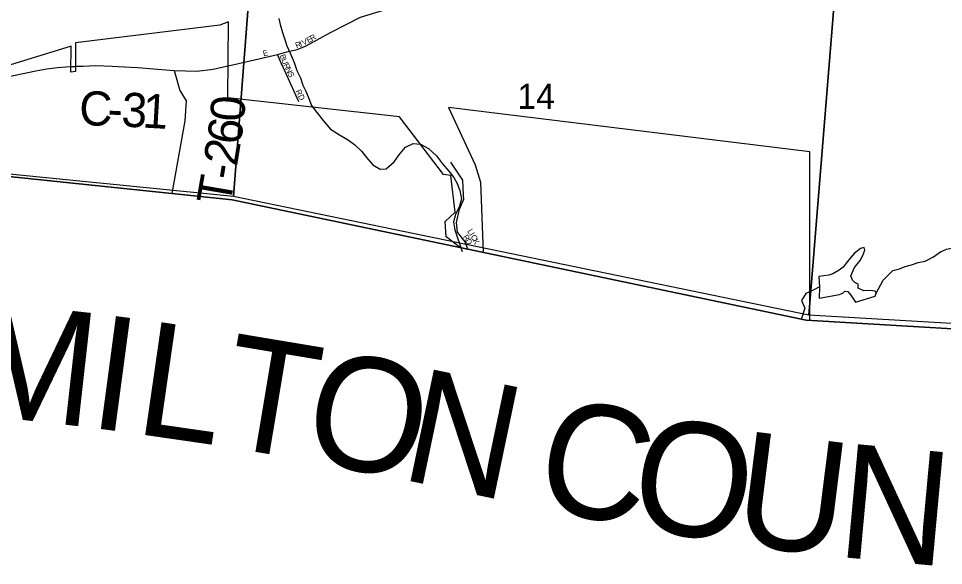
# Model space of a CAD drawing. Extents: x 1310247 to 1552180, y 377264 to 706493.
# Drawn here: x 1367792 to 1375909, y 481326 to 486127 of the extents above; entities that cross this region are included whole.
import ezdxf

# ---------------------------------------------------------------- set-up
doc = ezdxf.new("R2010")
doc.units = 0
for name, color, linetype in [('GM_X_Adjacent_County', 7, 'Continuous'), ('GM_X_Adjacent_County_Text', 7, 'Continuous'), ('GM_X_City_Street', 7, 'Continuous'), ('GM_X_City_Street_Text', 7, 'Continuous'), ('GM_X_Corporation', 7, 'Continuous'), ('GM_X_County', 7, 'Continuous'), ('GM_X_County_Road', 7, 'Continuous'), ('GM_X_County_Road_Text', 7, 'Continuous'), ('GM_X_Minor_River', 7, 'Continuous'), ('GM_X_Section', 7, 'Continuous'), ('GM_X_Section_Text', 7, 'Continuous'), ('GM_X_Township', 7, 'Continuous'), ('GM_X_Township_Road', 7, 'Continuous'), ('GM_X_Township_Road_Text', 7, 'Continuous')]:
    doc.layers.add(name, color=color, linetype=linetype)

msp = doc.modelspace()

# ---------------------------------------------------------------- linework, layer by layer
at = {"layer": 'GM_X_Adjacent_County'}
msp.add_lwpolyline([(1367312.1, 484779.9), (1369137.5, 484590.3), (1369667, 484535.3), (1371735.5, 484101.4), (1374704, 483478.8), (1379249.6, 483210.6), (1380075.5, 483161.9)], dxfattribs=at)
at = {"layer": 'GM_X_City_Street'}
for points in [[(1369824.4, 485755.1), (1369824.9, 485755.2), (1370064.8, 485810), (1370147.3, 485834.3), (1370237.5, 485855.9), (1370317, 485887.3), (1370530.1, 486004.4), (1370794.6, 486138), (1370994, 486198.7), (1371535, 486356), (1371847.8, 486445.8), (1372298, 486578.9), (1372444.1, 486634.9), (1372470.8, 486645.1)], [(1370250.9, 485396.8), (1370143.3, 485635.5), (1370099, 485728.7), (1370064.8, 485810)], [(1368250.3, 485704.3), (1368286.7, 485706.7), (1368303.8, 485707.4)], [(1371735.5, 484101.4), (1371710.5, 484166.5), (1371644.4, 484250.4), (1371636.5, 484337), (1371661.5, 484452.8), (1371699.8, 484542.3), (1371698.2, 484575.2), (1371698.1, 484576.3)]]:
    msp.add_lwpolyline(points, dxfattribs=at)
at = {"layer": 'GM_X_Corporation'}
msp.add_lwpolyline([(1380075.5, 483161.9), (1374735.4, 483477), (1374735, 484955.7), (1371565.2, 485345), (1371800.3, 484842.4), (1371847.2, 484689.1), (1371868.8, 484073.5), (1371669.5, 484115.3), (1371544.1, 484210.1), (1371536.3, 484343.6), (1371622.6, 484426.9), (1371587, 484749.7), (1371520.5, 484757.8), (1371135.2, 485263), (1369628.2, 485429.2), (1369633.9, 486096.7), (1369559.8, 486069.7), (1368293.4, 485914.2), (1368293.5, 485660.9), (1368251.6, 485655.1), (1368253.8, 485882.6), (1367101.3, 485530.2)], dxfattribs=at)
at = {"layer": 'GM_X_County'}
msp.add_lwpolyline([(1380075.5, 483161.9), (1379249.6, 483210.6), (1374704, 483478.8), (1371735.5, 484101.4), (1369667, 484535.3), (1369137.5, 484590.3), (1367312.1, 484779.9)], dxfattribs=at)
at = {"layer": 'GM_X_County_Road'}
for points in [[(1368838.8, 485695.4), (1368976.1, 485686.2), (1369159.3, 485671.2), (1369357.4, 485663.4), (1369500.7, 485681.3), (1369722.3, 485731.3), (1369824.4, 485755.1)], [(1366607, 484844.3), (1366958.7, 485194.1), (1367113.7, 485359.7), (1367209.7, 485442.2), (1367283.7, 485480.2), (1367408.4, 485524.6), (1367707.3, 485617.1), (1367943.1, 485667.1), (1368041.2, 485685.1), (1368135.6, 485695.5), (1368208.3, 485701.5), (1368250.3, 485704.3)], [(1368303.8, 485707.4), (1368359.4, 485709.7), (1368472.1, 485714.5), (1368615.4, 485709.7), (1368775.8, 485699.6), (1368838.8, 485695.4)]]:
    msp.add_lwpolyline(points, dxfattribs=at)
at = {"layer": 'GM_X_Minor_River'}
for points in [[(1370075.4, 486127.4), (1370087.9, 486072.8), (1370108.1, 486003.9), (1370128.5, 485941.1), (1370147.1, 485886.3), (1370175.4, 485821.2), (1370211.4, 485741.9), (1370235.5, 485670.9), (1370265.9, 485605.8), (1370288.2, 485540.8), (1370312.9, 485489.9), (1370339.2, 485424.9), (1370363.6, 485362), (1370410.1, 485300.4), (1370464.4, 485230.6), (1370530.6, 485156.5), (1370609.5, 485106.1), (1370680.6, 485064), (1370739.7, 485022.2), (1370806.2, 484960.1), (1370846.9, 484906.8), (1370901.3, 484841), (1370964.6, 484805.1), (1371018.8, 484807.6), (1371088.7, 484868.1), (1371130.4, 484927.2), (1371188.5, 484998), (1371255.6, 485030.4), (1371319.7, 485024.6), (1371388.9, 484984.6), (1371461.4, 484920.3), (1371511.7, 484852.6), (1371568.1, 484786.8), (1371612.8, 484731.3), (1371641.4, 484678.3), (1371663.8, 484617.4), (1371679.9, 484544.6), (1371662.1, 484478.8), (1371628, 484405.3), (1371610.2, 484341.5), (1371620.3, 484270.9), (1371686.8, 484082.2)], [(1374821.5, 483770.4), (1374818.9, 483672), (1374996.3, 483703.4), (1375024.8, 483716.7), (1375043.3, 483734.3), (1375069.3, 483731.6), (1375096.5, 483698.7), (1375119.6, 483661.9), (1375137, 483637.3), (1375311, 483690.9), (1375317.7, 483714.8), (1375308.2, 483733.2), (1375262.2, 483740.5), (1375210, 483737.8), (1375160.4, 483759.3), (1375159.3, 483795.5), (1375131.6, 483808.3), (1375110.2, 483831), (1375095.1, 483869.6), (1375127.2, 483941), (1375177.1, 484004), (1375202.3, 484047.5), (1375217.6, 484093.4), (1375214.3, 484117.6), (1375179.9, 484108.4), (1375126.5, 484063.7), (1375089.3, 484024.5)], [(1375317.7, 483714.8), (1375379, 483829.7), (1375465.6, 483913.8), (1375522.2, 483930.4), (1375572.9, 483949.1), (1375627.5, 483965.7), (1375686.2, 483984.2), (1375748.8, 483996.6), (1375822.1, 484034.8), (1375881.5, 484079.5), (1375936.3, 484102.1), (1375994.8, 484114.6), (1376063.2, 484120.8), (1376132.1, 484143)], [(1375089.3, 484024.5), (1375056, 483979.1), (1375028.9, 483943.7), (1374994.1, 483918.5), (1374937.1, 483885.9), (1374902.6, 483874.8), (1374816, 483863), (1374821.5, 483770.4)], [(1374821.5, 483770.4), (1374770.7, 483745.7), (1374701.6, 483713.4), (1374663.8, 483652.1), (1374692, 483583), (1374661.1, 483484.4)]]:
    msp.add_lwpolyline(points, dxfattribs=at)
at = {"layer": 'GM_X_Section'}
for points in [[(1375156.7, 488824.4), (1374727.4, 483521.8), (1369678.8, 484563.3), (1369911.3, 487554.2)], [(1369911.3, 487554.2), (1369678.8, 484563.3), (1365682.4, 484963.6)]]:
    msp.add_lwpolyline(points, dxfattribs=at)
msp.add_lwpolyline([(1375156.7, 488824.4), (1380602.9, 488643.8), (1380084.6, 483209.4), (1374727.4, 483521.8)], close=True, dxfattribs=at)
at = {"layer": 'GM_X_Township'}
msp.add_lwpolyline([(1380075.5, 483161.9), (1379249.6, 483210.6), (1374704, 483478.8), (1371735.5, 484101.4), (1369667, 484535.3), (1369137.5, 484590.3), (1367312.1, 484779.9)], dxfattribs=at)
at = {"layer": 'GM_X_Township_Road'}
for points in [[(1369159.3, 485671.2), (1369209, 485496.1), (1369262.6, 485404.2), (1369251.6, 485229.9), (1369137.5, 484590.3)], [(1371698.1, 484576.3), (1371691.8, 484707.1), (1371585.4, 484864.4)]]:
    msp.add_lwpolyline(points, dxfattribs=at)

# ---------------------------------------------------------------- texts
at = {"layer": 'GM_X_Adjacent_County_Text'}
for s, rotation, p in [('M', 353.59871, (1367318.2, 482660.6)), ('I', 352.39247, (1368392.7, 482540.1)), ('L', 351.78594, (1368795.5, 482486.3)), ('T', 350.50227, (1369530, 482380.4)), ('O', 348.88243, (1370260.4, 482258.3)), ('N', 348.18065, (1371125, 482088.4)), ('C', 348.46218, (1372293.3, 481843.8)), ('O', 350.29417, (1373125.2, 481674.5)), ('U', 352.83993, (1374044.9, 481518.3)), ('N', 354.74033, (1374958.4, 481404.2))]:
    msp.add_text(s, height=1000, rotation=rotation, dxfattribs=at).set_placement(p)
at = {"layer": 'GM_X_City_Street_Text'}
for s, rotation, p in [('E', 29.40387, (1370336.4, 485908.9)), ('R', 29.48054, (1370367.1, 485926.3)), ('R', 21.40454, (1370232.7, 485864.1)), ('I', 21.40429, (1370269.5, 485878.6)), ('V', 25.79118, (1370293.8, 485888.2)), ('E', 14.04106, (1369943.4, 485794)), ('B', 290.68965, (1370082.1, 485801.4)), ('U', 292.39156, (1370096.7, 485762.8)), ('R', 296.16625, (1370114.9, 485718.9)), ('N', 296.56742, (1370132.5, 485683)), ('S', 296.56506, (1370152.2, 485643.7)), ('RD', 295.2019, (1370222.6, 485489.7)), ('L', 301.01647, (1371728.7, 484260.8)), ('R', 303.59914, (1371689.7, 484209)), ('D', 299.19048, (1371711.1, 484176.9)), ('I', 301.01623, (1371746.8, 484230.6)), ('C', 298.74856, (1371757.9, 484212.2)), ('K', 296.56506, (1371776.7, 484177.9))]:
    msp.add_text(s, height=50, rotation=rotation, dxfattribs=at).set_placement(p)
at = {"layer": 'GM_X_County_Road_Text'}
for s, rotation, p in [('C', 359.1901, (1368324.4, 485189.1)), ('3', 356.9386, (1368690.7, 485180)), ('1', 356.81873, (1368875.1, 485170.1)), ('-', 357.34108, (1368568.2, 485185.7))]:
    msp.add_text(s, height=300, rotation=rotation, dxfattribs=at).set_placement(p)
at = {"layer": 'GM_X_Section_Text'}
msp.add_text('14', height=221, rotation=0.00001, dxfattribs=at).set_placement((1372169.8, 485333.7))
at = {"layer": 'GM_X_Township_Road_Text'}
for s, rotation, p in [('0', 85.26936, (1369769.4, 485213.9)), ('6', 81.43801, (1369739.3, 485009.4)), ('2', 80.58215, (1369708.3, 484822.3)), ('-', 80.30441, (1369687.3, 484699.3)), ('T', 80.23717, (1369649.2, 484477.8))]:
    msp.add_text(s, height=300, rotation=rotation, dxfattribs=at).set_placement(p)

doc.saveas('drawing.dxf')
